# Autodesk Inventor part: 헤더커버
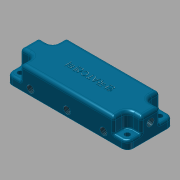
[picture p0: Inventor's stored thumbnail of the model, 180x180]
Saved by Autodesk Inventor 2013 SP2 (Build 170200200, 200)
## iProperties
Created: 2015-11
Part Number: 헤더커버
Material: 알루미늄 6061
Document SubType Name: Modeling
Designer: mduedu
Density: 2.71 g/cm^3
Author: mduedu
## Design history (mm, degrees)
sketch "스케치1"
  geometry: L1 (52.5, 20)-(-52.5, 20); L2 (-52.5, 20)-(-52.5, -20); L3 (-52.5, -20)-(52.5, -20); L4 (52.5, -20)-(52.5, 20); L5 (52.5, 20)-(-52.5, -20); L6 (-52.5, 20)-(52.5, -20); 1 further point
  constraints: 12 end point, 2 midpoint, 2 parallel, 1 horizontal, 1 perpendicular
  dimensions: "d0" = 105 distance of L3.end L2.end; "d1" = 40 distance of L2.end L1.end
extrude "돌출1" new body sketch "스케치1" distance "d2" = 20; taper "d3" = 0 deg
sketch "스케치2"
  geometry: L1 (-52.5, -20)-(-52.5, 20) reference; L2 (-52.5, 20)-(52.5, 20) reference; L3 (52.5, 20)-(52.5, -20) reference; L4 (52.5, -20)-(-52.5, -20) reference; L5 (-52.5, 20)-(-40.5, 20); L6 (-40.5, 20)-(-40.5, 8); L7 (-40.5, 8)-(-52.5, 8); L8 (-52.5, 8)-(-52.5, 20); L9 (52.5, 20)-(40.5, 20); L10 (40.5, 20)-(40.5, 8); L11 (40.5, 8)-(52.5, 8); L12 (52.5, 8)-(52.5, 20); L13 (52.5, -20)-(40.5, -20); L14 (40.5, -20)-(40.5, -8); L15 (40.5, -8)-(52.5, -8); L16 (52.5, -8)-(52.5, -20); L17 (-52.5, -20)-(-40.5, -20); L18 (-40.5, -20)-(-40.5, -8); L19 (-40.5, -8)-(-52.5, -8); L20 (-52.5, -8)-(-52.5, -20); 1 further point
  constraints: 32 end point, 8 parallel, 6 equal length, 4 horizontal, 4 perpendicular
  dimensions: "d4" = 12 distance of L6.end L7.end; "d5" = 12 distance of L5.end L6.end
extrude "돌출2" cut sketch "스케치2" distance "d6" = 13; taper "d7" = 0 deg
fillet "모깎기1" dims "d8" = 5
fillet "모깎기2" dims "d9" = 1
fillet "모깎기3" dims "d10" = 5
fillet "모깎기4" dims "d11" = 2
fillet "모깎기5" dims "d12" = 3
sketch "스케치3"
  geometry: L1 (-46.5, -14)-(46.5, -14); L2 (46.5, -14)-(46.5, 14); L3 (46.5, 14)-(-46.5, 14); L4 (-46.5, 14)-(-46.5, -14); L5 (-46.5, -14)-(46.5, 14); L6 (46.5, -14)-(-46.5, 14); L7 (47.5, 20)-(-47.5, 20) reference; L8 (52.5, -15)-(52.5, 15) reference; 5 further points
  constraints: 12 end point, 4 coincident, 2 midpoint, 2 parallel, 1 horizontal, 1 perpendicular
  dimensions: "d13" = 6 distance between parallel lines of L3 L7; "d14" = 6 distance between parallel lines of L2 L8
hole "구멍1" sketch "스케치3" at (-46.5, 14), (46.5, 14), (46.5, -14), (-46.5, -14) diameter "d15" = 4.5; stored, may be unused: countersink angle "d19" = 90 deg, drill point angle "d21" = 118 deg; dims "d16" = 6, "d17" = 4, "d18" = 2, "d20" = 8
sketch "스케치4"
  geometry: L1 (47.5, -20)-(-47.5, -20) reference; L2 (52.5, 15)-(52.5, -15) reference; L3 (-47.5, 20)-(47.5, 20) reference; L4 (-52.5, -15)-(-52.5, 15) reference; L5 (-52.5, 0)-(52.5, 0); C1 r 12.25 at (0, 0); C2 r 2.25 at (46.5, 14) reference; C3 r 2.25 at (-46.5, -14) reference; C4 r 2.25 at (46.5, -14) reference; C5 r 2.25 at (-46.5, 14) reference; C6 r 12.25 at (-32, 0); C7 r 12.25 at (32, 0); A1 r 5 centre (-47.5, -15) between (-52.5, -15) and (-47.5, -20) reference; A2 r 5 centre (47.5, -15) between (47.5, -20) and (52.5, -15) reference; A3 r 5 centre (47.5, 15) between (52.5, 15) and (47.5, 20) reference; A4 r 5 centre (-47.5, 15) between (-47.5, 20) and (-52.5, 15) reference; 1 further point
  constraints: 3 centre point, 2 end point, 2 midpoint, 2 point on line, 1 coincident
  dimensions: "d22" = 24.5 diameter of C1; "d23" = 24.5 diameter of C7 (= d22); "d24" = 24.5 diameter of C6 (= d22); "d25" = 32 distance of point (0, 0) C6.centre; "d26" = 32 distance of C7.centre point (0, 0) (= d25)
extrude "돌출3" cut sketch "스케치4" distance "d27" = 8; taper "d28" = 0 deg
fillet "모깎기6" dims "d29" = 5
sketch "스케치5"
  geometry: L1 (-52.5, 12)-(-47.119, 12); L2 (-40.191, 8)-(-37.635, 3.574); L3 (-52.5, 17)-(-52.5, 8) reference; L4 (-47.5, 0)-(-52.5, 0) reference; L5 (37.5, 20)-(-37.5, 20) reference; L6 (0, 0)-(0, 20); L7 (52.5, 12)-(47.119, 12); L8 (40.191, 8)-(37.635, 3.574); A1 r 8 centre (-47.119, 4) between (-40.191, 8) and (-47.119, 12); A2 r 8 centre (47.119, 4) between (47.119, 12) and (40.191, 8); 1 further point
  constraints: 10 end point, 5 symmetric about line, 4 point on circle, 3 point on line, 2 centre point, 2 tangent, 1 horizontal, 1 midpoint, 1 other
  dimensions: "d30" = 10 distance of L1.start point (-42.5, 12); "d32" = 120 deg angle of L2 L1; "d34" = 12 distance between parallel lines of L1 L4; "d35" = 8 radius of A1
sketch "스케치6"
  geometry: L1 (20, -5)-(20, 5) reference; L2 (8, -20)-(17, -20) reference; L3 (12, -20)-(12, -14.619); L4 (8, -7.691)-(3.81, -5.272); L5 (0, -20)-(0, -15) reference; A1 r 8 centre (4, -14.619) between (12, -14.619) and (8, -7.691); 2 further points
  constraints: 4 end point, 3 point on line, 2 point on circle, 2 tangent, 1 centre point, 1 perpendicular
  dimensions: "d36" = 10 distance of L3.start point (12, -10); "d38" = 12 distance between parallel lines of L3 L5; "d39" = 120 deg angle of L3 L4; "d40" = 8 radius of A1
node "작업점1"
node "작업점2"
node "작업점3"
hole "구멍2" diameter "d43" = 5.944; stored, may be unused: countersink angle "d49" = 90 deg, drill point angle "d51" = 0 deg; dims "d41" = 10, "d42" = 10, "d44" = 6.886, "d45" = 0.62479, "d46" = 5.959, "d47" = 4, "d48" = 2, "d50" = 6.9
hole "구멍3" diameter "d54" = 5.944; stored, may be unused: countersink angle "d60" = 90 deg, drill point angle "d62" = 0 deg; dims "d52" = 10, "d53" = 10, "d55" = 6.886, "d56" = 0.62479, "d57" = 5.959, "d58" = 4, "d59" = 2, "d61" = 6.9
hole "구멍4" diameter "d65" = 5.944; stored, may be unused: countersink angle "d71" = 90 deg, drill point angle "d73" = 0 deg; dims "d63" = 10, "d64" = 10, "d66" = 6.886, "d67" = 0.62479, "d68" = 5.959, "d69" = 4, "d70" = 2, "d72" = 6.9
sketch "스케치7"
  geometry: C1 r 2.972 at (15, 12) reference; 1 further point
sketch "스케치8"
  geometry: C1 r 2.972 at (15, 12) reference; 1 further point
sketch "스케치9"
  geometry: C1 r 2.972 at (47.5, 12) reference; 1 further point
feature "스윕1" dims "d74" = 0
feature "스윕2" dims "d75" = 0
feature "스윕3" dims "d76" = 0
sketch "스케치10"
  geometry: L1 (0, 0)-(95, 0) reference; L2 (22.75, 8)-(8.768, 8) reference; L3 (54.75, 8)-(40.25, 8) reference; L4 (86.232, 8)-(72.25, 8) reference; L5 (15.759, 8)-(15.759, 0); L6 (47.5, 8)-(47.5, 0); L7 (79.241, 8)-(79.241, 0); 5 further points
  constraints: 6 end point, 5 point on line, 3 midpoint, 2 horizontal alignment, 2 perpendicular, 1 parallel
  dimensions: "d77" = 5 distance from line of point (15.759, 5) L1
hole "구멍5" sketch "스케치10" at (15.759, 5), (47.5, 5), (79.241, 5) diameter "d78" = 5.944; stored, may be unused: countersink angle "d84" = 90 deg, drill point angle "d86" = 0 deg; dims "d79" = 6.886, "d80" = 0.62479, "d81" = 5.959, "d82" = 4, "d83" = 2, "d85" = 6.9
sketch "스케치11"
  geometry: C1 r 2.972 at (0, 0) reference; C2 r 2.972 at (31.741, 0) reference; C3 r 2.972 at (63.482, 0) reference; 1 further point
extrude "돌출4" cut sketch "스케치11" distance "d87" = 8; taper "d88" = 0 deg
sketch "스케치12"
  geometry: 2 further points
  constraints: 1 coincident, 1 other
feature "엠보싱1" sketch "스케치12" dims "d0" = 105, "d1" = 40, "d4" = 12, "d5" = 12, "d89" = 0.5, "d90" = 0
node "솔리드1"
node "투영된 루프1"
node "절단 모서리 투영1"
